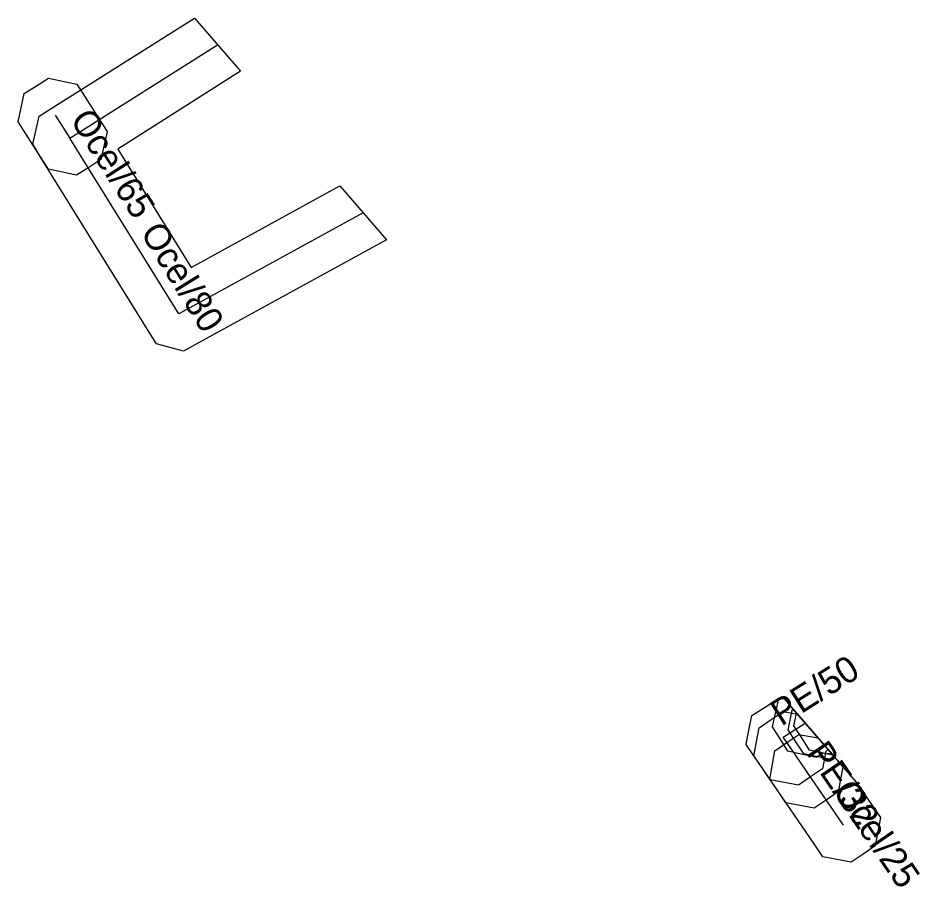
# Model space of a CAD drawing. Extents: x -647266 to -646926, y -1072084 to -1071793.
# Drawn here: x -647061.73 to -647035.84, y -1071920.76 to -1071895.81 of the extents above; entities that cross this region are included whole.
import ezdxf

# ---------------------------------------------------------------- set-up
doc = ezdxf.new("R2010")
doc.units = 0
for name, color, linetype in [('1', 7, 'Continuous'), ('24', 7, 'Continuous'), ('28', 7, 'Continuous'), ('30', 7, 'Continuous')]:
    doc.layers.add(name, color=color, linetype=linetype)

msp = doc.modelspace()

# ---------------------------------------------------------------- linework, layer by layer
at = {"layer": '1'}
for points in [[(-647060.778, -1071898.409), (-647056.668, -1071895.808), (-647055.344, -1071897.338), (-647058.871, -1071899.569), (-647056.765, -1071902.968), (-647052.495, -1071900.627), (-647051.156, -1071902.174), (-647056.635, -1071905.178), (-647056.985, -1071905.37), (-647057.756, -1071905.167), (-647057.966, -1071904.828), (-647060.767, -1071900.307), (-647061.093, -1071899.781), (-647061.31, -1071899.431), (-647061.126, -1071898.629)], [(-647060.047, -1071897.707), (-647059.823, -1071898.056), (-647059.401, -1071898.714), (-647059.177, -1071899.063), (-647059.354, -1071899.872), (-647059.703, -1071900.096), (-647060.052, -1071900.32), (-647060.861, -1071900.143), (-647061.085, -1071899.794), (-647061.507, -1071899.136), (-647061.731, -1071898.787), (-647061.554, -1071897.978), (-647061.205, -1071897.754), (-647060.856, -1071897.53)], [(-647040.305, -1071915.608), (-647039.8, -1071915.288), (-647038.477, -1071916.817), (-647038.547, -1071916.861), (-647038.641, -1071917.366), (-647038.983, -1071917.6), (-647039.325, -1071917.834), (-647040.139, -1071917.682), (-647040.373, -1071917.34), (-647040.594, -1071917.017), (-647040.834, -1071916.666), (-647040.749, -1071916.251), (-647040.663, -1071915.835)], [(-647039.895, -1071915.348), (-647039.8, -1071915.288), (-647038.362, -1071916.949), (-647038.63, -1071916.914), (-647038.822, -1071917.036), (-647039.631, -1071916.856), (-647039.853, -1071916.506), (-647040.075, -1071916.157)], [(-647039.625, -1071916.242), (-647039.497, -1071915.639), (-647038.274, -1071917.051), (-647038.365, -1071917.11), (-647039.175, -1071916.938), (-647039.4, -1071916.59)], [(-647039.364, -1071915.792), (-647038.054, -1071917.305), (-647038.19, -1071918.027), (-647038.532, -1071918.261), (-647038.874, -1071918.495), (-647039.687, -1071918.342), (-647039.921, -1071918), (-647040.373, -1071917.339), (-647040.607, -1071916.997), (-647040.454, -1071916.184), (-647040.112, -1071915.95), (-647039.77, -1071915.716)], [(-647039.458, -1071916.132), (-647039.381, -1071915.773), (-647038.343, -1071916.971), (-647039.008, -1071916.828), (-647039.233, -1071916.48)], [(-647038.769, -1071916.48), (-647037.672, -1071917.746), (-647037.21, -1071918.421), (-647036.976, -1071918.763), (-647037.128, -1071919.577), (-647037.47, -1071919.811), (-647037.812, -1071920.045), (-647038.626, -1071919.893), (-647038.86, -1071919.551), (-647039.921, -1071918.001), (-647040.155, -1071917.659), (-647040.003, -1071916.845), (-647039.661, -1071916.611), (-647039.319, -1071916.377)]]:
    msp.add_lwpolyline(points, close=True, dxfattribs=at)
at = {"layer": '24'}
for points in [[(-647051.826, -1071901.401), (-647057.116, -1071904.301), (-647059.917, -1071899.78), (-647060.243, -1071899.254), (-647056.006, -1071896.573)], [(-647060.665, -1071898.596), (-647060.243, -1071899.254)]]:
    msp.add_lwpolyline(points, dxfattribs=at)
at = {"layer": '28'}
for points in [[(-647039.548, -1071916.775), (-647039.769, -1071916.452), (-647039.139, -1071916.052)], [(-647039.096, -1071917.436), (-647039.548, -1071916.775)], [(-647038.035, -1071918.986), (-647039.096, -1071917.436)]]:
    msp.add_lwpolyline(points, dxfattribs=at)

# ---------------------------------------------------------------- texts
at = {"layer": '30'}
for s, rotation, p in [('Ocel/65', 302.6736, (-647060.254, -1071898.725)), ('Ocel/80', 301.7804, (-647058.237, -1071901.968)), ('PE/50', 32.3833, (-647039.819, -1071916.157)), ('PE/32', 304.3648, (-647039.122, -1071916.906)), ('Ocel/25', 304.3923, (-647038.366, -1071918.011))]:
    msp.add_text(s, height=0.75, rotation=rotation, dxfattribs=at).set_placement(p)

doc.saveas('drawing.dxf')
